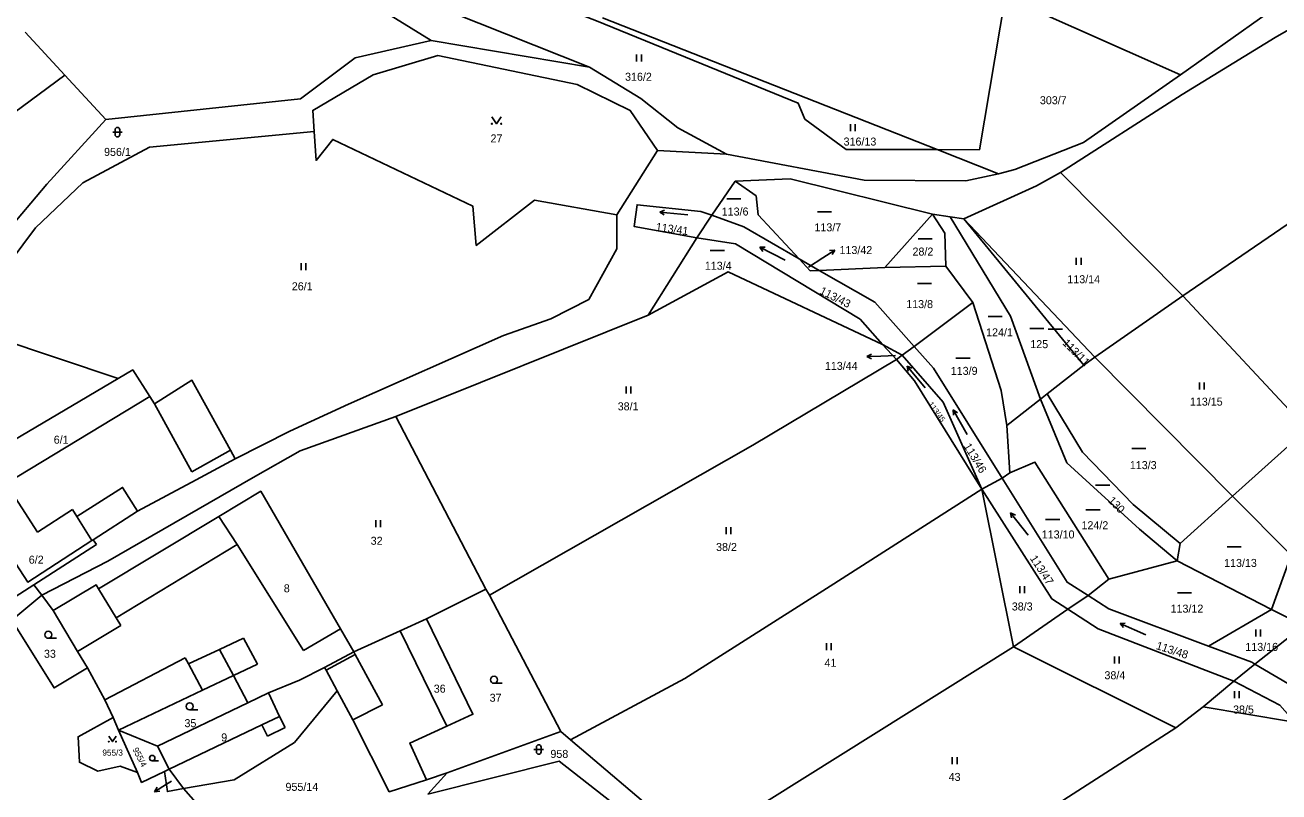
# Model space of a CAD drawing. Extents: x -7476540 to -746055, y -11317203 to -1129777.
# Drawn here: x -747812.8 to -747546.5, y -1130986.6 to -1130823.7 of the extents above; entities that cross this region are included whole.
import ezdxf

# ---------------------------------------------------------------- set-up
doc = ezdxf.new("R2010")
doc.units = 0
for name, color, linetype in [('Hranice parcel', 7, 'Continuous'), ('Parcelní čísla', 7, 'Continuous'), ('Pop  PČ popisy', 7, 'Continuous'), ('Vnitřní kresba', 7, 'Continuous'), ('Značky kultur', 7, 'Continuous')]:
    doc.layers.add(name, color=color, linetype=linetype)

msp = doc.modelspace()

# ---------------------------------------------------------------- linework, layer by layer
at = {"layer": 'Hranice parcel'}
for p, q in [((-747567.45, -1130834.27), (-747601.44, -1130819.19)), ((-747690.17, -1130822.16), (-747619.1, -1130850.16)), ((-747812.81, -1130825.22), (-747804.38, -1130834.32)), ((-747692.92, -1130832.64), (-747726.57, -1130826.97)), ((-747804.38, -1130834.32), (-747840.03, -1130860.79)), ((-747804.38, -1130834.32), (-747795.63, -1130843.76)), ((-747687.14, -1130864.03), (-747678.53, -1130850.34)), ((-747678.53, -1130850.34), (-747663.88, -1130851.09)), ((-747606.08, -1130855.29), (-747619.1, -1130850.16)), ((-747566.95, -1130881.22), (-747592.89, -1130855.02)), ((-747666.96, -1130864.06), (-747662, -1130856.84)), ((-747670.15, -1130868.87), (-747666.96, -1130864.06)), ((-747620.11, -1130863.87), (-747630.22, -1130875.23)), ((-747620.11, -1130863.87), (-747616.32, -1130864.44)), ((-747616.32, -1130864.44), (-747613.42, -1130864.85)), ((-747585.62, -1130894.26), (-747613.42, -1130864.85)), ((-747613.42, -1130864.85), (-747587.99, -1130895.92)), ((-747670.15, -1130868.87), (-747680.49, -1130885.34)), ((-747648.43, -1130873.34), (-747644.19, -1130875.8)), ((-747644.19, -1130875.8), (-747630.22, -1130875.23)), ((-747630.22, -1130875.23), (-747617.27, -1130874.92)), ((-747611.5, -1130882.62), (-747617.27, -1130874.92)), ((-747585.62, -1130894.26), (-747566.95, -1130881.22)), ((-747540.5, -1130909.52), (-747566.95, -1130881.22)), ((-747624, -1130891.96), (-747611.5, -1130882.62)), ((-747734.07, -1130906.85), (-747680.49, -1130885.34)), ((-747825.73, -1130887.83), (-747793.01, -1130898.76)), ((-747627.71, -1130894.75), (-747630.73, -1130891.53)), ((-747630.73, -1130891.53), (-747626.52, -1130893.83)), ((-747626.52, -1130893.83), (-747624, -1130891.96)), ((-747627.71, -1130894.75), (-747626.52, -1130893.83)), ((-747585.62, -1130894.26), (-747587.99, -1130895.92)), ((-747556.37, -1130923.79), (-747585.62, -1130894.26)), ((-747587.99, -1130895.92), (-747595.75, -1130902.05)), ((-747604.33, -1130908.77), (-747597.18, -1130903.17)), ((-747597.18, -1130903.17), (-747595.75, -1130902.05)), ((-747714.93, -1130943.52), (-747734.07, -1130906.85)), ((-747603.65, -1130918.79), (-747604.33, -1130908.77)), ((-747556.37, -1130923.79), (-747540.5, -1130909.52)), ((-747605.27, -1130919.98), (-747603.65, -1130918.79)), ((-747609.63, -1130922.29), (-747605.27, -1130919.98)), ((-747609.63, -1130922.29), (-747602.88, -1130955.82)), ((-747567.53, -1130933.83), (-747556.37, -1130923.79)), ((-747810.2, -1130931.39), (-747802.76, -1130926.61)), ((-747798.33, -1130933.02), (-747788.95, -1130926.93)), ((-747810.92, -1130942.58), (-747797.65, -1130934.06)), ((-747798.61, -1130933.2), (-747798.33, -1130933.02)), ((-747797.65, -1130934.06), (-747798.33, -1130933.02)), ((-747567.53, -1130933.83), (-747568.14, -1130937.53)), ((-747568.14, -1130937.53), (-747582.67, -1130941.38)), ((-747548.12, -1130947.84), (-747568.14, -1130937.53)), ((-747809.25, -1130944.84), (-747810.92, -1130942.58)), ((-747587.06, -1130944.87), (-747582.67, -1130941.38)), ((-747809.25, -1130944.84), (-747806.85, -1130948.1)), ((-747727.56, -1130949.81), (-747714.93, -1130943.52)), ((-747714.21, -1130944.8), (-747714.93, -1130943.52)), ((-747699.04, -1130973.8), (-747714.21, -1130944.8)), ((-747591.34, -1130947.8), (-747587.06, -1130944.87)), ((-747602.88, -1130955.82), (-747591.34, -1130947.8)), ((-747561.51, -1130955.61), (-747548.12, -1130947.84)), ((-747544.17, -1130949.82), (-747548.12, -1130947.84)), ((-747551.66, -1130959.44), (-747542.97, -1130952.61)), ((-747670.43, -1130998.05), (-747602.88, -1130955.82)), ((-747602.88, -1130955.82), (-747568.39, -1130973)), ((-747749.19, -1130960.19), (-747743.01, -1130956.84)), ((-747556.12, -1130963.07), (-747551.66, -1130959.44)), ((-747562.63, -1130968.51), (-747556.12, -1130963.07)), ((-747765.48, -1130967.66), (-747784.66, -1130976.88)), ((-747568.39, -1130973), (-747562.63, -1130968.51)), ((-747794.11, -1130970.77), (-747792.94, -1130973.48)), ((-747788.92, -1130982.46), (-747792.94, -1130973.48)), ((-747792.94, -1130973.48), (-747784.66, -1130976.88)), ((-747723.14, -1130982.58), (-747699.04, -1130973.8)), ((-747696.99, -1130975.53), (-747699.04, -1130973.8)), ((-747784.66, -1130976.88), (-747782.22, -1130981.78)), ((-747670.43, -1130998.05), (-747696.99, -1130975.53)), ((-747783.2, -1130982.29), (-747782.22, -1130981.78)), ((-747782.22, -1130981.78), (-747779.16, -1130985.88)), ((-747727.55, -1130984.01), (-747723.14, -1130982.58)), ((-747727.26, -1130987.09), (-747723.14, -1130982.58)), ((-747774.01, -1130991.73), (-747779.16, -1130985.88))]:
    msp.add_line(p, q, dxfattribs=at)
for points in [[(-747592.89, -1130855.02), (-747567.07, -1130838.41), (-747547.35, -1130826.32), (-747527.53, -1130814.88), (-747492.89, -1130797.06), (-747472.69, -1130787.42), (-747441.69, -1130763.28), (-747417.46, -1130747.1), (-747393.87, -1130731.74)], [(-747566.95, -1130881.22), (-747540.53, -1130863.15), (-747518.65, -1130845.8), (-747451.1, -1130789.94), (-747421.34, -1130761.04), (-747390.31, -1130735.18)], [(-747726.57, -1130826.97), (-747749.62, -1130812.66), (-747757.07, -1130798.44), (-747753.28, -1130789.29)], [(-747751.97, -1130797.81), (-747746.34, -1130810.93), (-747722.32, -1130820.98), (-747692.92, -1130832.64)], [(-747518.4, -1130801.96), (-747535.86, -1130812.1), (-747550.62, -1130822.39), (-747567.45, -1130834.27)], [(-747619.1, -1130850.16), (-747638.4, -1130850.1), (-747647.23, -1130843.67), (-747648.62, -1130840.27), (-747691.42, -1130822.76), (-747716.64, -1130813.01), (-747715.36, -1130812.23)], [(-747619.1, -1130850.16), (-747610.15, -1130850.19), (-747604.68, -1130817.79)], [(-747795.63, -1130843.76), (-747754.3, -1130839.33), (-747742.68, -1130830.62), (-747726.57, -1130826.97)], [(-747678.53, -1130850.34), (-747684.28, -1130841.87), (-747695.55, -1130836.35), (-747725.17, -1130830.16), (-747738.86, -1130834.29), (-747751.71, -1130841.81), (-747751.43, -1130846.33)], [(-747692.92, -1130832.64), (-747682.03, -1130839.3), (-747674.17, -1130845.51), (-747663.88, -1130851.09)], [(-747567.45, -1130834.27), (-747588.01, -1130848.67), (-747602.62, -1130854.39), (-747606.08, -1130855.29)], [(-747831.64, -1130880.59), (-747825.65, -1130878.15), (-747808.21, -1130857.46), (-747795.63, -1130843.76)], [(-747751.43, -1130846.33), (-747786.35, -1130849.61), (-747800.53, -1130857.22), (-747810.62, -1130866.79), (-747823.91, -1130884.54), (-747825.73, -1130887.83)], [(-747687.14, -1130864.03), (-747704.65, -1130860.86), (-747717, -1130870.51), (-747717.72, -1130862.13), (-747747.45, -1130847.99), (-747751.02, -1130852.43), (-747751.43, -1130846.33)], [(-747663.88, -1130851.09), (-747634.6, -1130856.66), (-747613, -1130856.77), (-747606.08, -1130855.29)], [(-747613.42, -1130864.85), (-747598.03, -1130857.85), (-747592.89, -1130855.02)], [(-747662, -1130856.84), (-747650.32, -1130856.36), (-747620.11, -1130863.87)], [(-747648.43, -1130873.34), (-747657.11, -1130864.01), (-747657.53, -1130859.98), (-747662, -1130856.84)], [(-747670.15, -1130868.87), (-747683.44, -1130866.5), (-747682.82, -1130861.87), (-747669.33, -1130863.29), (-747666.96, -1130864.06)], [(-747768.2, -1130915.84), (-747756.58, -1130909.94), (-747744.11, -1130904.25), (-747711.23, -1130889.62), (-747701.16, -1130886.13), (-747693.1, -1130881.99), (-747687.11, -1130871.26), (-747687.14, -1130864.03)], [(-747666.96, -1130864.06), (-747660.13, -1130866.55), (-747648.43, -1130873.34)], [(-747617.27, -1130874.92), (-747617.49, -1130867.91), (-747620.11, -1130863.87)], [(-747597.18, -1130903.17), (-747603.54, -1130885.52), (-747616.32, -1130864.44)], [(-747630.73, -1130891.53), (-747635.43, -1130886.18), (-747661.9, -1130870.18), (-747670.15, -1130868.87)], [(-747648.43, -1130873.34), (-747646.1, -1130875.88), (-747644.19, -1130875.8)], [(-747680.49, -1130885.34), (-747663.47, -1130876.12), (-747630.73, -1130891.53)], [(-747644.19, -1130875.8), (-747632.37, -1130882.58), (-747624, -1130891.96)], [(-747604.33, -1130908.77), (-747605.55, -1130901.3), (-747611.5, -1130882.62)], [(-747624, -1130891.96), (-747619.89, -1130896.55), (-747605.27, -1130919.98)], [(-747714.21, -1130944.8), (-747658.27, -1130912.95), (-747627.71, -1130894.75)], [(-747609.63, -1130922.29), (-747623.92, -1130899.27), (-747627.71, -1130894.75)], [(-747609.63, -1130922.29), (-747617.8, -1130903.81), (-747626.52, -1130893.83)], [(-747786.33, -1130902.63), (-747789.93, -1130896.95), (-747793.01, -1130898.76)], [(-747793.01, -1130898.76), (-747820.31, -1130914.83), (-747821.04, -1130913.77), (-747826.88, -1130917.6)], [(-747768.2, -1130915.84), (-747769.2, -1130914.03), (-747777.39, -1130899.14), (-747785.31, -1130904.19), (-747786.33, -1130902.63)], [(-747568.14, -1130937.53), (-747576.11, -1130930.77), (-747591.59, -1130916.72), (-747597.18, -1130903.17)], [(-747595.75, -1130902.05), (-747588.22, -1130914.45), (-747577.5, -1130925.53), (-747567.53, -1130933.83)], [(-747734.07, -1130906.85), (-747754.36, -1130914.15), (-747764.38, -1130919.82), (-747795.26, -1130937.61), (-747809.25, -1130944.84)], [(-747788.95, -1130926.93), (-747776.49, -1130920.27), (-747768.2, -1130915.84)], [(-747582.67, -1130941.38), (-747598.35, -1130916.55), (-747603.65, -1130918.79)], [(-747822.35, -1130924.58), (-747816.84, -1130921.05), (-747810.2, -1130931.39)], [(-747802.76, -1130926.61), (-747801.79, -1130928.13), (-747792.11, -1130921.93), (-747788.95, -1130926.93)], [(-747605.27, -1130919.98), (-747591.5, -1130942.05), (-747587.06, -1130944.87)], [(-747743.01, -1130956.84), (-747745.82, -1130951.95), (-747762.77, -1130922.74), (-747771.66, -1130928.1), (-747797.2, -1130943.47), (-747797.72, -1130942.61), (-747806.85, -1130948.1)], [(-747696.99, -1130975.53), (-747672.66, -1130962.51), (-747641.8, -1130942.93), (-747609.63, -1130922.29)], [(-747591.34, -1130947.8), (-747594.77, -1130945.6), (-747609.63, -1130922.29)], [(-747548.12, -1130947.84), (-747543.96, -1130936.32), (-747556.37, -1130923.79)], [(-747810.92, -1130942.58), (-747816.91, -1130946.43), (-747824.59, -1130933.96), (-747819.12, -1130930.45)], [(-747819.12, -1130930.45), (-747816.13, -1130935.12), (-747816.51, -1130935.36), (-747812.22, -1130942.04), (-747798.61, -1130933.2)], [(-747809.25, -1130944.84), (-747815.62, -1130950.1), (-747806.65, -1130964.52), (-747799.54, -1130960.27)], [(-747587.06, -1130944.87), (-747582.62, -1130947.7), (-747561.51, -1130955.61)], [(-747806.85, -1130948.1), (-747801.65, -1130956.79), (-747799.54, -1130960.27)], [(-747556.12, -1130963.07), (-747584.92, -1130951.93), (-747591.34, -1130947.8)], [(-747727.56, -1130949.81), (-747733.16, -1130952.36), (-747743.01, -1130956.84)], [(-747727.55, -1130984.01), (-747731.13, -1130976.23), (-747723.26, -1130972.63), (-747717.69, -1130970.09), (-747727.56, -1130949.81)], [(-747561.51, -1130955.61), (-747552.29, -1130959.07), (-747551.66, -1130959.44)], [(-747799.54, -1130960.27), (-747795.87, -1130967.04), (-747794.11, -1130970.77)], [(-747792.94, -1130973.48), (-747775.11, -1130965.02), (-747768.52, -1130961.91), (-747765.48, -1130967.66)], [(-747765.48, -1130967.66), (-747761.14, -1130965.57), (-747754.52, -1130962.87), (-747749.19, -1130960.19)], [(-747746.53, -1130965.11), (-747748.88, -1130960.76), (-747749.19, -1130960.19)], [(-747551.66, -1130959.44), (-747542.61, -1130964.81), (-747533.86, -1130974.48), (-747529.57, -1130980.67)], [(-747533.76, -1130983.87), (-747538.28, -1130977.32), (-747546.35, -1130968.19), (-747556.12, -1130963.07)], [(-747779.16, -1130985.88), (-747768.38, -1130984.02), (-747755.59, -1130976.12), (-747746.53, -1130965.11)], [(-747746.53, -1130965.11), (-747743.17, -1130971.3), (-747735.45, -1130986.58), (-747727.55, -1130984.01)], [(-747562.63, -1130968.51), (-747544.05, -1130971.62), (-747534.58, -1130984.5)], [(-747788.92, -1130982.46), (-747792.6, -1130981.16), (-747797.32, -1130982.19), (-747801.28, -1130980.31), (-747801.56, -1130974.89), (-747794.11, -1130970.77)], [(-747647.48, -1131019.78), (-747615.24, -1131003.06), (-747568.39, -1130973)], [(-747641.15, -1131027.46), (-747677.24, -1130997.39), (-747699.35, -1130980.06), (-747727.26, -1130987.09)], [(-747783.2, -1130982.29), (-747788.06, -1130984.58), (-747788.92, -1130982.46)], [(-747779.16, -1130985.88), (-747782.56, -1130986.54), (-747783.2, -1130982.29)]]:
    msp.add_lwpolyline(points, dxfattribs=at)
at = {"layer": 'Pop  PČ popisy'}
for p, q in [((-747646.42, -1130875.1), (-747643.37, -1130873.12)), ((-747643.37, -1130873.12), (-747640.85, -1130871.49)), ((-747640.85, -1130871.49), (-747641.97, -1130871.61)), ((-747640.85, -1130871.49), (-747641.42, -1130872.45)), ((-747634.05, -1130894.11), (-747633.07, -1130893.58)), ((-747631.05, -1130894.01), (-747634.05, -1130894.11)), ((-747634.05, -1130894.11), (-747633.03, -1130894.58)), ((-747627.99, -1130893.91), (-747631.05, -1130894.01)), ((-747782.79, -1130984.99), (-747785.33, -1130986.58)), ((-747785.33, -1130986.58), (-747784.75, -1130985.62)), ((-747781.73, -1130984.34), (-747782.79, -1130984.99)), ((-747785.33, -1130986.58), (-747784.22, -1130986.47))]:
    msp.add_line(p, q, dxfattribs=at)
at = {"layer": 'Vnitřní kresba'}
for p, q in [((-747786.33, -1130902.63), (-747816.84, -1130921.05)), ((-747785.31, -1130904.19), (-747777.39, -1130918.63)), ((-747769.2, -1130914.03), (-747777.39, -1130918.63)), ((-747801.79, -1130928.13), (-747798.61, -1130933.2)), ((-747767.79, -1130934.01), (-747771.66, -1130928.1)), ((-747793.47, -1130949.63), (-747767.79, -1130934.01)), ((-747753.68, -1130956.54), (-747767.79, -1130934.01)), ((-747797.2, -1130943.47), (-747793.47, -1130949.63)), ((-747801.65, -1130956.79), (-747792.49, -1130951.26)), ((-747793.47, -1130949.63), (-747792.49, -1130951.26)), ((-747766.45, -1130953.93), (-747771.54, -1130956.35)), ((-747763.42, -1130959.49), (-747766.45, -1130953.93)), ((-747753.68, -1130956.54), (-747745.82, -1130951.95)), ((-747733.16, -1130952.36), (-747723.26, -1130972.63)), ((-747771.54, -1130956.35), (-747778.1, -1130959.43)), ((-747771.54, -1130956.35), (-747768.52, -1130961.91)), ((-747778.81, -1130958.12), (-747795.87, -1130967.04)), ((-747778.81, -1130958.12), (-747778.1, -1130959.43)), ((-747748.88, -1130960.76), (-747742.69, -1130957.41)), ((-747742.69, -1130957.41), (-747743.01, -1130956.84)), ((-747736.92, -1130968.11), (-747742.69, -1130957.41)), ((-747778.1, -1130959.43), (-747775.11, -1130965.02)), ((-747768.52, -1130961.91), (-747763.42, -1130959.49)), ((-747761.14, -1130965.57), (-747758.74, -1130970.57)), ((-747743.17, -1130971.3), (-747736.92, -1130968.11)), ((-747762.53, -1130972.38), (-747782.22, -1130981.78)), ((-747758.74, -1130970.57), (-747762.53, -1130972.38)), ((-747761.33, -1130974.79), (-747762.53, -1130972.38)), ((-747758.74, -1130970.57), (-747757.54, -1130972.91)), ((-747757.54, -1130972.91), (-747761.33, -1130974.79))]:
    msp.add_line(p, q, dxfattribs=at)
at = {"layer": 'Značky kultur'}
for p, q in [((-747682.93, -1130831.43), (-747682.93, -1130829.93)), ((-747681.93, -1130831.43), (-747681.93, -1130829.93)), ((-747637.49, -1130846.23), (-747637.49, -1130844.73)), ((-747636.49, -1130846.23), (-747636.49, -1130844.73)), ((-747794.18, -1130846.44), (-747792.18, -1130846.44)), ((-747793.68, -1130845.94), (-747793.68, -1130846.94)), ((-747792.68, -1130846.94), (-747792.68, -1130845.94)), ((-747663.77, -1130860.61), (-747660.77, -1130860.61)), ((-747678.02, -1130863.41), (-747677, -1130863.01)), ((-747672.05, -1130864.03), (-747678.02, -1130863.41)), ((-747678.02, -1130863.41), (-747677.1, -1130864.01)), ((-747644.55, -1130863.36), (-747641.55, -1130863.36)), ((-747651.4, -1130873.63), (-747656.74, -1130870.9)), ((-747656.74, -1130870.9), (-747656.1, -1130871.79)), ((-747656.74, -1130870.9), (-747655.65, -1130870.9)), ((-747623.17, -1130869.11), (-747620.17, -1130869.11)), ((-747667.28, -1130871.61), (-747664.28, -1130871.61)), ((-747589.56, -1130874.63), (-747589.56, -1130873.13)), ((-747588.56, -1130874.63), (-747588.56, -1130873.13)), ((-747754.2, -1130875.77), (-747754.2, -1130874.27)), ((-747753.2, -1130875.77), (-747753.2, -1130874.27)), ((-747623.28, -1130878.56), (-747620.28, -1130878.56)), ((-747608.3, -1130885.57), (-747605.3, -1130885.57)), ((-747599.42, -1130888.17), (-747596.42, -1130888.17)), ((-747595.5, -1130888.31), (-747592.5, -1130888.31)), ((-747615.13, -1130894.45), (-747612.13, -1130894.45)), ((-747621.66, -1130900.75), (-747625.51, -1130896.15)), ((-747625.51, -1130896.15), (-747625.27, -1130897.22)), ((-747625.51, -1130896.15), (-747624.5, -1130896.58)), ((-747685.15, -1130901.99), (-747685.15, -1130900.49)), ((-747684.15, -1130901.99), (-747684.15, -1130900.49)), ((-747563.38, -1130901.11), (-747563.38, -1130899.61)), ((-747562.38, -1130901.11), (-747562.38, -1130899.61)), ((-747612.71, -1130910.64), (-747615.71, -1130905.44)), ((-747615.71, -1130905.44), (-747615.66, -1130906.54)), ((-747615.71, -1130905.44), (-747614.79, -1130906.04)), ((-747577.79, -1130913.63), (-747574.79, -1130913.63)), ((-747585.47, -1130921.44), (-747582.47, -1130921.44)), ((-747599.81, -1130932.05), (-747603.5, -1130927.33)), ((-747603.5, -1130927.33), (-747603.29, -1130928.41)), ((-747603.5, -1130927.33), (-747602.5, -1130927.79)), ((-747587.5, -1130926.66), (-747584.5, -1130926.66)), ((-747738.33, -1130930.36), (-747738.33, -1130928.86)), ((-747737.33, -1130930.36), (-747737.33, -1130928.86)), ((-747596.08, -1130928.75), (-747593.08, -1130928.75)), ((-747663.89, -1130931.87), (-747663.89, -1130930.37)), ((-747662.89, -1130931.87), (-747662.89, -1130930.37)), ((-747557.53, -1130934.52), (-747554.53, -1130934.52)), ((-747601.56, -1130944.39), (-747601.56, -1130942.89)), ((-747600.56, -1130944.39), (-747600.56, -1130942.89)), ((-747568.07, -1130944.3), (-747565.07, -1130944.3)), ((-747580.24, -1130950.82), (-747579.15, -1130950.76)), ((-747574.76, -1130953.27), (-747580.24, -1130950.82)), ((-747580.24, -1130950.82), (-747579.55, -1130951.68)), ((-747807.88, -1130953.97), (-747806.13, -1130953.97)), ((-747551.41, -1130953.59), (-747551.41, -1130952.09)), ((-747550.41, -1130953.59), (-747550.41, -1130952.09)), ((-747642.63, -1130956.48), (-747642.63, -1130954.98)), ((-747641.63, -1130956.48), (-747641.63, -1130954.98)), ((-747581.47, -1130959.36), (-747581.47, -1130957.86)), ((-747580.47, -1130959.36), (-747580.47, -1130957.86)), ((-747713.22, -1130963.53), (-747711.47, -1130963.53)), ((-747555.95, -1130966.7), (-747555.95, -1130965.2)), ((-747554.95, -1130966.7), (-747554.95, -1130965.2)), ((-747777.86, -1130969.18), (-747776.11, -1130969.18)), ((-747704.73, -1130977.6), (-747702.73, -1130977.6)), ((-747704.23, -1130977.1), (-747704.23, -1130978.1)), ((-747703.23, -1130978.1), (-747703.23, -1130977.1)), ((-747785.82, -1130980), (-747784.47, -1130980)), ((-747615.89, -1130980.72), (-747615.89, -1130979.22)), ((-747614.89, -1130980.72), (-747614.89, -1130979.22))]:
    msp.add_line(p, q, dxfattribs=at)
for points in [[(-747713.68, -1130843.16), (-747712.68, -1130844.66), (-747711.68, -1130843.16)], [(-747795.02, -1130974.76), (-747794.25, -1130975.92), (-747793.48, -1130974.76)]]:
    msp.add_lwpolyline(points, dxfattribs=at)
for centre, radius in [((-747713.68, -1130844.66), 0.1), ((-747711.68, -1130844.66), 0.1), ((-747807.88, -1130953.22), 0.75), ((-747713.22, -1130962.78), 0.75), ((-747777.86, -1130968.43), 0.75), ((-747795.02, -1130975.92), 0.077), ((-747793.48, -1130975.92), 0.077), ((-747785.81, -1130979.42), 0.577)]:
    msp.add_circle(centre, radius, dxfattribs=at)
for centre, start, end in [((-747793.18, -1130845.94), 0, 180), ((-747793.18, -1130846.94), 180, 359.9879), ((-747703.73, -1130977.1), 0, 180), ((-747703.73, -1130978.1), 180, 359.9879)]:
    msp.add_arc(centre, 0.5, start, end, dxfattribs=at)

# ---------------------------------------------------------------- texts
at = {"layer": 'Parcelní čísla'}
for s, height, p in [('316/2', 1.7, (-747685.39, -1130835.52)), ('303/7', 1.7, (-747597.29, -1130840.51)), ('27', 1.7, (-747713.96, -1130848.62)), ('956/1', 1.7, (-747796.03, -1130851.49)), ('316/13', 1.7, (-747638.98, -1130849.29)), ('113/6', 1.7, (-747664.86, -1130864.16)), ('113/7', 1.7, (-747645.17, -1130867.51)), ('113/42', 1.7, (-747639.85, -1130872.34)), ('28/2', 1.7, (-747624.34, -1130872.66)), ('113/4', 1.7, (-747668.45, -1130875.67)), ('113/14', 1.7, (-747591.46, -1130878.54)), ('26/1', 1.7, (-747756.16, -1130880.04)), ('113/8', 1.7, (-747625.68, -1130883.82)), ('124/1', 1.7, (-747608.71, -1130889.82)), ('125', 1.7, (-747599.33, -1130892.33)), ('113/44', 1.7, (-747642.95, -1130896.95)), ('113/9', 1.7, (-747616.22, -1130898)), ('113/15', 1.7, (-747565.43, -1130904.54)), ('38/1', 1.7, (-747686.95, -1130905.54)), ('6/1', 1.7, (-747806.72, -1130912.63)), ('113/3', 1.7, (-747578.19, -1130918.03)), ('124/2', 1.7, (-747588.46, -1130930.8)), ('32', 1.7, (-747739.41, -1130934.1)), ('113/10', 1.7, (-747596.89, -1130932.76)), ('38/2', 1.7, (-747666.06, -1130935.42)), ('6/2', 1.7, (-747812.02, -1130938.12)), ('113/13', 1.7, (-747558.17, -1130938.81)), ('8', 1.7, (-747757.86, -1130944.2)), ('38/3', 1.7, (-747603.26, -1130948.06)), ('113/12', 1.7, (-747569.54, -1130948.52)), ('33', 1.7, (-747808.79, -1130958.11)), ('113/16', 1.7, (-747553.66, -1130956.65)), ('41', 1.7, (-747643.03, -1130960.03)), ('38/4', 1.7, (-747583.58, -1130962.67)), ('36', 1.7, (-747726.02, -1130965.52)), ('37', 1.7, (-747714.15, -1130967.45)), ('38/5', 1.7, (-747556.27, -1130969.95)), ('35', 1.7, (-747778.96, -1130972.85)), ('9', 1.7, (-747771.15, -1130975.87)), ('955/3', 1.304, (-747796.39, -1130978.91)), ('958', 1.7, (-747701.24, -1130979.38)), ('43', 1.7, (-747616.67, -1130984.27)), ('955/14', 1.7, (-747757.5, -1130986.38))]:
    msp.add_text(s, height=height, dxfattribs=at).set_placement(p)
for s, height, rotation, p in [('113/41', 1.7, 352, (-747678.95, -1130867.36)), ('113/43', 1.7, 333, (-747644.22, -1130880.69)), ('113/11', 1.7, 315, (-747592.63, -1130891.39)), ('113/45', 1.14, 306, (-747621.03, -1130904.24)), ('113/46', 1.7, 301, (-747613.54, -1130913.13)), ('130', 1.7, 314, (-747582.94, -1130924.84)), ('113/47', 1.7, 303, (-747599.48, -1130936.99)), ('113/48', 1.7, 342, (-747572.75, -1130956.22)), ('955/4', 1.304, 297, (-747790.02, -1130977.57))]:
    msp.add_text(s, height=height, rotation=rotation, dxfattribs=at).set_placement(p)

doc.saveas('drawing.dxf')
